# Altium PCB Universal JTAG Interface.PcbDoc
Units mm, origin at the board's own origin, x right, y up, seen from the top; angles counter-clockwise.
Board outline 60 x 39.3 mm, 2 copper layers (Top Layer, Bottom Layer); 81 components, 60 nets, 244 pads, 77 vias.
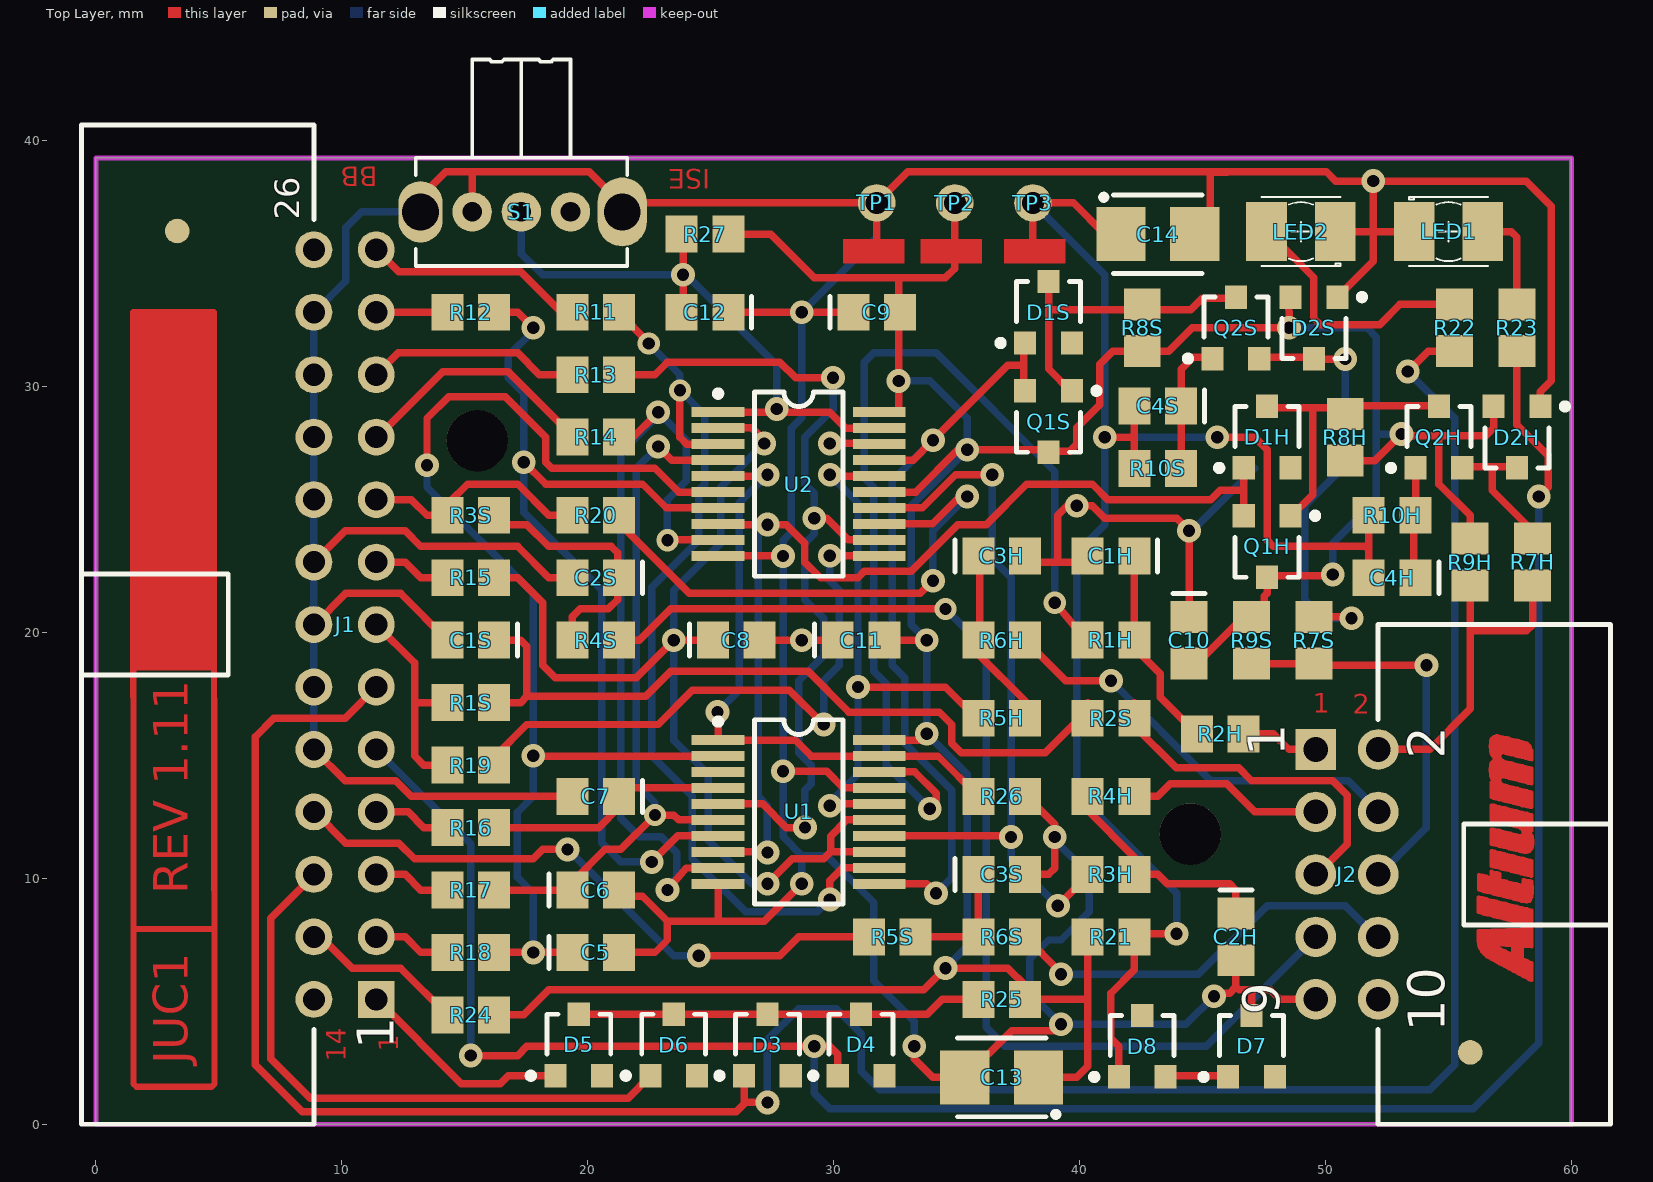
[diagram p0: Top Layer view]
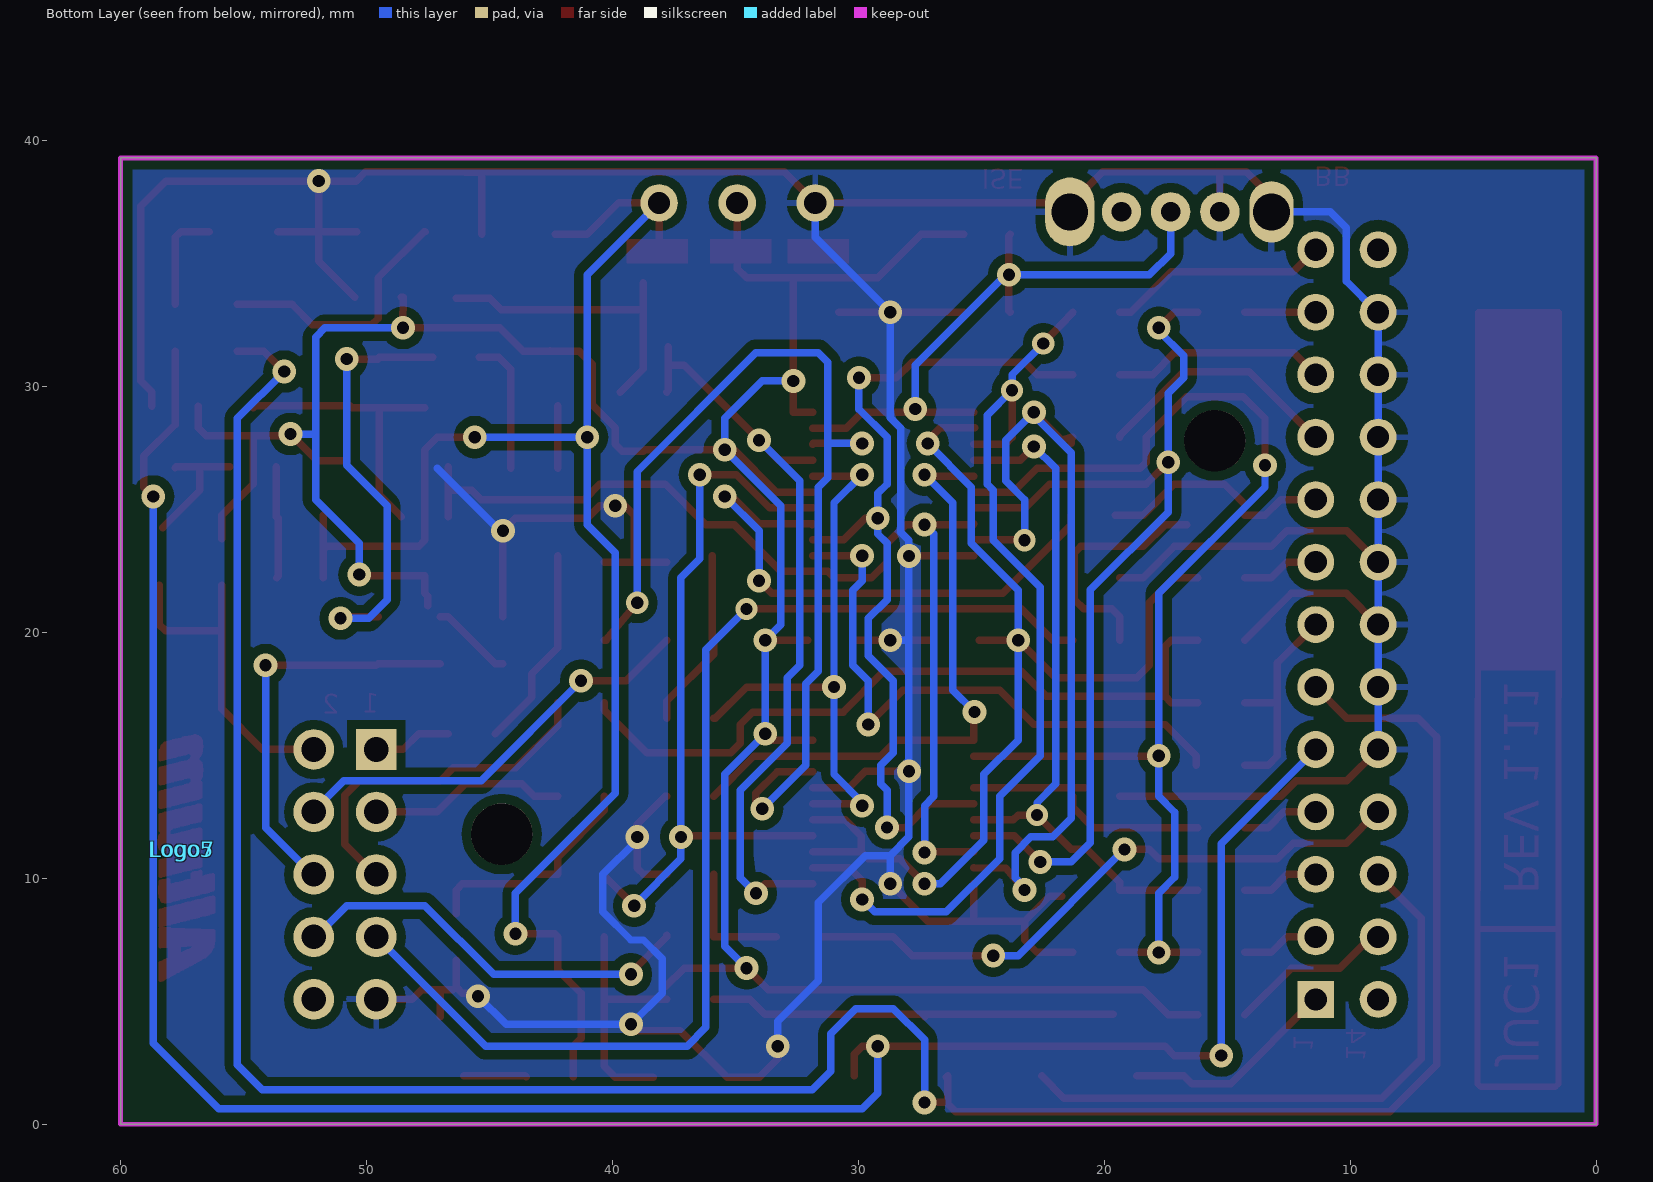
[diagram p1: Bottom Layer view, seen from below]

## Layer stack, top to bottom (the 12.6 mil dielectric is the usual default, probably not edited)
Top Layer: signal copper 0.0356
Dielectric: dielectric 0.32, FR-4, Dk 4.8
Bottom Layer: signal copper 0.0356

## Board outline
0,0 60,0 60,39.3 0,39.3

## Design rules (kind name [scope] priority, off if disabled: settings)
Clearance "Polygon Clearance" [InPolygon] p1: gap=0.381
Clearance "Via-Via Clearance" [IsVia vs IsVia] p2: gap=0.3
Clearance "Via-SMD Pad Clearance" [IsVia vs IsPad And OnTopLayer] p3: gap=0.254
Clearance "Via-Pad Clearance" [IsVia vs IsPad] p4: gap=0.3
Clearance "IC Pad-Pad Clearance" [HasFootprint('SOP65P780-20') vs HasFootprint('SOP65P780-20')] p5: gap=0.203
Clearance "General Clearance" [All] p6: gap=0.254
ComponentClearance ComponentClearance_General [Not InComponent('Logo5') && Not InComponent('Logo7') vs Not InComponent('Logo5') && Not InComponent('Logo7')] p1: gap=0.254 collisioncheckmode=3 verticalgap=0.254 showdistances=FALSE
ComponentClearance ComponentClearance_Default [All] p2 off: gap=0.254 collisioncheckmode=3 verticalgap=0.254 showdistances=FALSE
FabricationTestPointUsage TestPointUsage [All] p1 off: valid=0 allowmultiple=FALSE
FabricationTestpoint Testpoint [All] p1 off: side=3 testpointundercomponent=TRUE minsize=1.016 maxsize=2.54 preferedsize=1.524 minholesize=0 maxholesize=1.016 preferedholesize=0.813 testpointgrid=0.025 allowsidetop=TRUE allowsidebottom=TRUE usegrid=TRUE gridtolerance=0
HoleSize [All] p1: absolutevalues=TRUE maxlimit=3.2 minlimit=0.4 maxpercent=80.000 minpercent=20.000
PolygonConnect [All] p1: connectstyle=Relief reliefconductorwidth=0.254 reliefentries=4 polygonreliefangle="90 Angle"
RoutingVias [All] p1: holewidth=0.483 width=0.965 viastyle="Through Hole" minholewidth=0.3 minwidth=0.6 maxholewidth=0.711 maxwidth=1.27
SMDNeckDown [All] p1: percent=90.000
SilkscreenOverComponentPads [All] p1: minsilkscreentomaskgap=0.254
SolderMaskExpansion [All] p1: expansion=0.102
Width "Logo Component Track Width" [InComponent('Logo5') Or InComponent('Logo7')] p1: maxlimit=2.54 minlimit=0.127 preferedwidth=0.254
Width "Polygon Width" [InPolygon] p2: maxlimit=0.508 minlimit=0.203 preferedwidth=0.254
Width [All] p3: maxlimit=1.27 minlimit=0.254 preferedwidth=0.305
23 further rules are at their usual default settings.

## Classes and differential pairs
component class H: C1H C2H C3H C4H D1H D2H Q1H Q2H R1H R2H R3H R4H R5H R6H R7H R8H R9H R10H
component class "Universal JTAG Interface": C5 C6 C7 C8 C9 C10 C11 C12 C13 C14 D3 D4 D5 D6 D7 D8 J1 J2 LED1 LED2 R11 R12 R13 R14 R15 R16 R17 R18 R19 R20 R21 R22 R23 R24 R25 R26 R27 S1 TP1 TP2 TP3 U1 U2
component class S: C1S C2S C3S C4S D1S D2S Q1S Q2S R1S R2S R3S R4S R5S R6S R7S R8S R9S R10S
channel class "JTAG Interface": H S

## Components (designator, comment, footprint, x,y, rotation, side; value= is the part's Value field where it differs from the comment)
C1H "47pF 50V" CAPC2012 41.275,23.114 r180 top (schematic designator C1)
C1S "47pF 50V" CAPC2012 15.24,19.685 r180 top (schematic designator C1)
C2H "47pF 50V" CAPC2012 46.355,7.62 r270 top (schematic designator C2)
C2S "47pF 50V" CAPC2012 20.32,22.225 r180 top (schematic designator C2)
C3H "47pF 50V" CAPC2012 36.83,23.114 r0 top (schematic designator C3)
C3S "47pF 50V" CAPC2012 36.83,10.16 r0 top (schematic designator C3)
C4H "47pF 50V" CAPC2012 52.705,22.225 r180 top (schematic designator C4)
C4S "47pF 50V" CAPC2012 43.18,29.21 r180 top (schematic designator C4)
C5 "47pF 50V" CAPC2012 20.32,6.985 r0 top
C6 "47pF 50V" CAPC2012 20.32,9.525 r0 top
C7 "47pF 50V" CAPC2012 20.32,13.335 r180 top
C8 "47pF 50V" CAPC2012 26.035,19.685 r0 top
C9 "10nF 50V" CAPC2012 31.75,33.02 r0 top
C10 "10nF 50V" CAPC2012 44.45,19.685 r270 top
C11 "10nF 50V" CAPC2012 31.115,19.685 r0 top
C12 "10nF 50V" CAPC2012 24.765,33.02 r180 top
C13 "10uF 16V" CAPC3528 36.83,1.905 r180 top
C14 "10uF 16V" CAPC3528 43.18,36.195 r0 top
D1H "200mA 30V" SOT95P230-3 47.625,27.94 r0 top (schematic designator D1)
D1S "200mA 30V" SOT95P230-3 38.735,33.02 r0 top (schematic designator D1)
D2H "215mA 85V" SOT95P230-3 57.785,27.94 r180 top (schematic designator D2)
D2S "215mA 85V" SOT95P230-3 49.53,32.385 r180 top (schematic designator D2)
D3 "200mA 30V" SOT95P230-3 27.305,3.225 r0 top
D4 "200mA 30V" SOT95P230-3 31.115,3.225 r0 top
D5 "200mA 30V" SOT95P230-3 19.635,3.225 r0 top
D6 "200mA 30V" SOT95P230-3 23.495,3.225 r0 top
D7 "200mA 30V" SOT95P230-3 46.99,3.175 r0 top
D8 "215mA 85V" SOT95P230-3 42.545,3.175 r0 top
J1 "2x13 RA HEADER" HDR2X13_RA_CENTRONICS 8.86,20.32 r90 top locked
J2 "2x5 RA HEADER" 918510x323 52.14,10.16 r270 top locked
LED1 "ORANGE" LED3528 55,36.3 r180 top locked
LED2 "ORANGE" LED3528 49,36.3 r0 top
Logo5 "" "Altium Logo Small Bottom"#1 57.534,11.167 r270 bottom
Logo7 "" "Altium Logo Small Bottom"#2 57.495,11.167 r270 bottom
Q1H "TRAN-NPN-75V-40V-6V-SOT23" SOT95P230-3 47.625,23.495 r180 top (schematic designator Q1)
Q1S "TRAN-NPN-75V-40V-6V-SOT23" SOT95P230-3 38.735,28.575 r180 top (schematic designator Q1)
Q2H "TRAN-NPN-75V-40V-6V-SOT23" SOT95P230-3 54.61,27.94 r0 top (schematic designator Q2)
Q2S "TRAN-NPN-75V-40V-6V-SOT23" SOT95P230-3 46.355,32.385 r0 top (schematic designator Q2)
R1H "47R 5%" RESC2012 41.275,19.685 r0 top (schematic designator R1)
R1S "47R 5%" RESC2012 15.24,17.145 r0 top (schematic designator R1)
R2H "47R 5%" RESC2012 45.72,15.875 r0 top (schematic designator R2)
R2S "47R 5%" RESC2012 41.275,16.51 r0 top (schematic designator R2)
R3H "47R 5%" RESC2012 41.275,10.16 r0 top (schematic designator R3)
R3S "47R 5%" RESC2012 15.24,24.765 r0 top (schematic designator R3)
R4H "47R 5%" RESC2012 41.275,13.335 r0 top (schematic designator R4)
R4S "47R 5%" RESC2012 20.32,19.685 r0 top (schematic designator R4)
R5H "47R 5%" RESC2012 36.83,16.51 r0 top (schematic designator R5)
R5S "47R 5%" RESC2012 32.385,7.62 r0 top (schematic designator R5)
R6H "47R 5%" RESC2012 36.83,19.685 r0 top (schematic designator R6)
R6S "47R 5%" RESC2012 36.83,7.62 r0 top (schematic designator R6)
R7H "47R 5%" RESC2012 58.42,22.86 r90 top (schematic designator R7)
R7S "47R 5%" RESC2012 49.53,19.685 r90 top (schematic designator R7)
R8H "2K2 5%" RESC2012 50.8,27.94 r270 top (schematic designator R8)
R8S "2K2 5%" RESC2012 42.545,32.385 r270 top (schematic designator R8)
R9H "6K8 5%" RESC2012 55.88,22.86 r90 top (schematic designator R9)
R9S "6K8 5%" RESC2012 46.99,19.685 r90 top (schematic designator R9)
R10H "470R 5%" RESC2012 52.705,24.765 r0 top (schematic designator R10)
R10S "470R 5%" RESC2012 43.18,26.67 r0 top (schematic designator R10)
R11 "47R 5%" RESC2012 20.32,33.02 r180 top
R12 "47R 5%" RESC2012 15.24,33.02 r180 top
R13 "47R 5%" RESC2012 20.32,30.48 r180 top
R14 "47R 5%" RESC2012 20.32,27.94 r180 top
R15 "47R 5%" RESC2012 15.24,22.225 r180 top
R16 "47R 5%" RESC2012 15.24,12.065 r180 top
R17 "47R 5%" RESC2012 15.24,9.525 r180 top
R18 "47R 5%" RESC2012 15.24,6.985 r180 top
R19 "47R 5%" RESC2012 15.24,14.605 r0 top
R20 "47R 5%" RESC2012 20.32,24.765 r0 top
R21 "2K2 5%" RESC2012 41.275,7.62 r180 top
R22 "220R 5%" RESC2012 55.245,32.385 r270 top
R23 "220R 5%" RESC2012 57.785,32.385 r270 top
R24 "6K8 5%" RESC2012 15.24,4.445 r180 top
R25 "22R 5%" RESC2012 36.83,5.08 r180 top
R26 "47K 5%" RESC2012 36.83,13.335 r0 top
R27 "47K 5%" RESC2012 24.765,36.195 r180 top
S1 "SPDT SUB" OS102011MA1QN1 17.3,37.1 r180 top locked
TP1 "(GND)" TestPin 31.75,37.465 r0 top
TP2 "(VCC)" TestPin 34.925,37.465 r90 top
TP3 "(Vref)" TestPin 38.1,37.465 r90 top
U1 "SN74LVC244ADB" SOP65P780-20 28.575,12.7 r270 top
U2 "SN74LVC244ADB" SOP65P780-20 28.575,26.035 r270 top

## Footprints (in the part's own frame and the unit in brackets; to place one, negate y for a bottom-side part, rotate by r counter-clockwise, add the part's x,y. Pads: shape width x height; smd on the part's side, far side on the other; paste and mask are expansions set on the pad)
918510x323 [mm]
  rect 1.65x1.65 hole 1: 1(-5.08,-2.54)
  round 1.65 hole 1: 2(-5.08,0) 3(-2.54,-2.54) 4(-2.54,0) 5(0,-2.54) 6(0,0) 7(2.54,-2.54) 8(2.54,0) 9(5.08,-2.54) 10(5.08,0)
  silkscreen extent -10.16,0 10.16,9.45
"Altium Logo Small Bottom"#1 [mm]
  Bottom Layer drawing of 687 lines, arcs and shapes, not listed
"Altium Logo Small Bottom"#2 [mm]
CAPC2012 [mm]
  rect 1.3x1.5 smd: 1(-0.95,0) 2(0.95,0)
  silkscreen extent -1.9,-0.65 -1.9,0.65
CAPC3528 [mm]
  rect 2x2.2 smd: 1(-1.5,0) 2(1.5,0)
  silkscreen extent -2.3,-1.6 1.8,1.6
HDR2X13_RA_CENTRONICS [mm]
  rect 1.5x1.5 hole 0.9: 1(-15.24,-2.54)
  round 1.5 hole 0.9: 2(-12.7,-2.54) 3(-10.16,-2.54) 4(-7.62,-2.54) 5(-5.08,-2.54) 6(-2.54,-2.54) 7(0,-2.54) 8(2.54,-2.54) 9(5.08,-2.54) 10(7.62,-2.54) 11(10.16,-2.54) 12(12.7,-2.54) 13(15.24,-2.54) 14(-15.24,0) 15(-12.7,0) 16(-10.16,0) 17(-7.62,0) 18(-5.08,0) 19(-2.54,0) 20(0,0) 21(2.54,0) 22(5.08,0) 23(7.62,0) 24(10.16,0) 25(12.7,0) 26(15.24,0)
  silkscreen extent -20.32,0 20.32,9.45
LED3528 [mm]
  rect 1.65x2.41 smd: 1(-1.4,0) 2(1.4,0)
  silkscreen extent -1.6,-1.4 1.6,1.4
OS102011MA1QN1 [mm]
  round 1.6 hole 0.8: 1(-2,0) 2(0,0) 3(2,0)
  oval 2x2.8 / inner round 2 / far side oval 2x2.8 hole 1.5: M1(-4.1,0)
  oval 1.8x2.5 / inner oval 1.8x2 / far side oval 1.8x2.5 hole 1.5: M2(4.1,0)
  silkscreen extent -4.3,-6.2 4.3,2.2
RESC2012 [mm]
  rect 1.3x1.5 smd: 1(-0.95,0) 2(0.95,0)
SOP65P780-20 [mm]
  rect 0.4x2.15 smd: 1(-2.925,-3.275) 2(-2.275,-3.275) 3(-1.625,-3.275) 4(-0.975,-3.275) 5(-0.325,-3.275) 6(0.325,-3.275) 7(0.975,-3.275) 8(1.625,-3.275) 9(2.275,-3.275) 10(2.925,-3.275) 11(2.925,3.275) 12(2.275,3.275) 13(1.625,3.275) 14(0.975,3.275) 15(0.325,3.275) 16(-0.325,3.275) 17(-0.975,3.275) 18(-1.625,3.275) 19(-2.275,3.275) 20(-2.925,3.275)
  silkscreen extent -3.8,-3.4 3.75,1.8
SOT95P230-3 [mm]
  rect 0.9x0.95 smd: 1(-0.95,-1.25) 2(0.95,-1.25) 3(0,1.25)
  silkscreen extent -2.07,-1.37 1.3,1.25
TestPin [mil]
  round 60 hole 35.43: 1(0,0)

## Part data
C1H C1S C2H C2S C3H C3S C4H C4S C5 C6 C7 C8 C9 C10 C11 C12: library part CAP-NP, "Capacitor"
C13 C14: library part CAP-P, "Polar Capacitor"
D1H D1S D3 D4 D5 D6 D7: library part DIO-SCHOTTKY-1S-SOT23, "Schottky Barrier Single Diode"
D2H D2S D8: library part DIO-2S, "Silicon Switching Diode Array for High-Speed Switching"
J1: library part CON-IDC-2x13-M-RA, "Header, 13-Pin, Dual row"
J2: library part CON-IDC-2x5-M-RA, "Header, 5-Pin, Dual row, Right angle boxed"
LED1 LED2: library part DIO-LED-1S, "Typical GREEN SMD LED Agilent make"
Q1H Q1S Q2H Q2S: library part TRA-NPN, "General Purpose Transistor NPN Silicon"
R1H R1S R2H R2S R3H R3S R4H R4S R5H R5S R6H R6S R7H R7S R8H R8S R9H R9S R10H R10S R11 R12 R13 R14 R15 R16 R17 R18 R19 R20 R21 R22 R23 R24 R25 R26 R27: library part RES, "Resistor"
S1: library part SWI-TOG-SPDT-OS102011MA1QN1, "SPDT Subminiature Toggle Switch"
TP1 TP2 TP3: library part TestPin
U1 U2: library part SN74LVC244, "Octal Buffer/Driver with 3-State Outputs"

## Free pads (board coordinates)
  round 2.49 hole 2.5 unplated: 0(15.5,27.8) 1(44.5,11.8)
  round 1 smd mask+1.6: FID(3.302,36.322) FID(55.88,2.921)

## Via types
v1: diameter 0.965, hole 0.5, Top Layer to Bottom Layer, tented both sides, 71 vias
v2: diameter 0.9, hole 0.5, Top Layer to Bottom Layer, tented both sides, 6 vias

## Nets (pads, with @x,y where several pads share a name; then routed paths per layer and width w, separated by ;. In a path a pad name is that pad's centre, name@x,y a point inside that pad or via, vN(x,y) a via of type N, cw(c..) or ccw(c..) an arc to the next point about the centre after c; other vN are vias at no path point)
BB/I\S\E\: R26.1 U1.1 U1.19 U2.5 | length 25.2
  Top Layer w0.305: v1(25.273,16.764) 25.3,16.483 U1.1 28.444,15.625 29.094,14.975 U1.19 34.24,14.975 R26.1 ; U2.5 27.249,26.36 v1(27.305,26.416)
  Bottom Layer w0.305: v1(25.273,16.764) 26.162,17.653 26.162,25.273 v1(27.305,26.416)
"COMPATIBILITY MODE": C12.2 R27.2 S1.2 U2.1 U2.19 | length 25.8
  Top Layer w0.305: C12.2 23.876,33.081 v1(23.876,34.544) 23.876,36.134 R27.2 ; U2.1 27.686,28.96 29.841,28.96 30.491,28.31 U2.19
  Bottom Layer w0.305: S1.2 17.3,35.405 18.161,34.544 v1(23.876,34.544) 24.003,34.544 27.686,30.861 v1(27.686,29.087)
GND: C1H.2 C1S.2 C2H.2 C2S.2 C3H.2 C3S.2 C5.2 C6.2 C7.2 C8.2 C9.1 C10.1 C11.1 C12.1 C13.2 C14.2 D2H.1 D2S.1 D7.3 J1.18 J1.19 J1.20 J1.21 J1.22 J1.23 J1.24 J1.25 J2.9 LED1.2 LED2.2 R26.2 S1.3 S1.M1 S1.M2 TP1.1 U1.10 U1.17 U2.10 | length 248
  Top Layer w0.305: J1.18 10.13,13.97 12.192,13.97 12.827,13.335 C7.2 ; J1.20 8.89,20.32 10.16,21.59 12.385,21.59 C1S.2 ; J1.21 10.13,24.13 12.573,24.13 13.208,23.495 17.145,23.495 18.415,22.225 C2S.2 ; S1.M2@13.208,37.719 14.224,38.735 15.367,38.735 ; S1.3 15.3,38.668 15.367,38.735 ; C5.2 22.733,6.985 23.241,7.493 23.241,8.255 ; S1.M1 21.4,37.401 20.066,38.735 15.367,38.735 ; C6.2@21.717,9.271 22.225,9.271 23.241,8.255 ; S1.M1@21.971,37.592 22.098,37.465 TP1.1 ; U1.10@25.296,9.779 U1.10 25.3,8.282 ; U2.10 v1(27.94,23.11) ; C12.1 v1(28.702,33.02) C9.1 ; C8.2 v1(28.702,19.685) C11.1 ; v1(27.94,14.351) 29.718,14.351 30.394,13.675 U1.17 ; v1@28.698,9.775 27.178,8.255 23.241,8.255 ; 31.75,35.687 TP1.1 ; v1(33.274,3.175) 33.274,2.667 34.036,1.905 C13.2 37.235,3.81 38.989,3.81 v1(39.243,4.064) ; C3S.2 38.735,10.16 38.989,10.414 v1(38.989,11.684) 38.989,12.192 37.846,13.335 R26.2 ; C3H.2@37.78,22.86 39.116,22.86 ; C1H.2@40.325,22.86 39.116,22.86 ; C10.1 v1(44.45,24.13) 43.942,24.638 41.021,24.638 40.513,25.146 v1(39.878,25.146) 39.497,25.146 39.116,24.765 39.116,22.86 ; C14.2@45.315,36.195 45.315,38.711 ; v1(45.466,5.207) 45.593,5.334 46.101,5.334 46.355,5.588 ; 45.998,38.711 45.315,38.711 ; C2H.2 46.355,5.588 ; D7.3@46.99,4.375 46.99,5.461 ; J2.9 48.133,5.08 47.752,5.461 46.99,5.461 ; LED2.2 51.921,36.3 ; D2S.1 51.943,35.098 51.943,36.3 ; LED1.2 51.943,36.3 ; D2H.1 58.735,29.779 59.182,30.226 59.182,37.338 58.166,38.354 v1(51.943,38.354) ; TP1.1 33.02,38.735 45.339,38.735 ; 45.315,38.711 45.339,38.735 ; 45.339,38.735 50.038,38.735 50.419,38.354 v1(51.943,38.354) ; 46.355,5.588 46.482,5.461 46.99,5.461 ; 51.921,36.3 51.943,36.322 ; 51.921,36.3 51.943,36.3 ; 51.943,36.3 51.943,36.322 ; 51.943,36.322 v1(51.943,38.354)
  Bottom Layer w0.305: J1.18 J1.19 J1.20 J1.21 J1.22 J1.23 J1.24 J1.25 8.89,33.02 10.16,34.29 10.16,36.449 10.811,37.1 S1.M2 ; v1(28.702,9.779) 28.702,10.922 ; v1(28.702,19.685) 28.067,19.685 27.94,19.812 ; TP1.1 31.75,36.068 v1(28.702,33.02) 28.702,28.73 28.27,28.298 28.27,24.079 27.94,23.749 v1(27.94,23.11) 27.94,19.812 ; v1(33.274,3.175) 33.274,4.191 31.623,5.842 31.623,9.017 29.718,10.922 28.702,10.922 ; v1(38.989,11.684) 38.989,11.557 40.386,10.16 40.386,8.636 39.243,7.493 38.735,7.493 37.973,6.731 37.973,5.334 v1(39.243,4.064) 44.323,4.064 v1(45.466,5.207) ; v1(44.45,24.13) 44.577,24.13 47.117,26.67 ; v1@51.89,38.376 v1@51.9,38.4 ; 27.94,19.812 v1(27.94,14.351) 27.94,11.684 28.702,10.922
HARD-TCK: J2.3 R4H.2 | length 8.1
  Top Layer w0.305: R4H.2 43.18,13.335 43.688,13.843 45.974,13.843 47.117,12.7 J2.3
HARD-TDI: J2.1 R2H.2 | length 3.2
  Top Layer w0.305: R2H.2 47.879,15.875 48.514,15.24 J2.1
HARD-TDO: J2.2 R7H.1 R9H.1 | length 13.7
  Top Layer w0.305: J2.2 54.229,15.24 55.88,16.891 55.88,20.066 ; R9H.1 55.88,20.066 ; R7H.1 58.42,20.32 58.166,20.066 55.88,20.066
HARD-TMS: J2.4 R6H.2 | length 17.3
  Top Layer w0.305: R6H.2 39.431,18.034 v1(41.275,18.034)
  Bottom Layer w0.305: v1(41.275,18.034) 45.339,13.97 50.927,13.97 52.14,12.757 J2.4
HARD_TCK_IN: R3H.1 U1.14 U2.14 | length 30.9
  Top Layer w0.305: U1.14 v1@37.17,11.725 ; U2.14 33.597,25.06 34.953,26.416 v1(36.449,26.416) ; v1(39.116,8.89) 40.325,10.099 R3H.1
  Bottom Layer w0.305: v1(36.449,26.416) 36.449,22.987 37.211,22.225 v1(37.211,11.684) 37.211,10.795 v1(39.116,8.89)
HARD_TDI_IN: R1H.1 U1.18 U2.18 | length 43.4
  Top Layer w0.305: v1(29.845,27.686) 31.824,27.686 U2.18 ; U1.18 33.3,14.325 34.163,13.462 34.163,13.081 v1(33.909,12.827) ; v2(38.989,21.209) 40.259,19.685 R1H.1
  Bottom Layer w0.305: v1(29.845,27.686) 31.242,27.686 ; v1(33.909,12.827) 32.131,14.605 32.131,17.907 31.623,18.415 31.623,25.908 31.242,26.289 31.242,27.686 ; v2(38.989,21.209) 38.989,26.543 34.163,31.369 31.623,31.369 31.242,30.988 31.242,27.686
HARD_TDO_OUT: D1H.1 Q1H.2 U1.8 U2.8 | length 42.4
  Top Layer w0.305: U1.8 v1@27.279,11.075 ; U2.8 25.326,24.384 v1(27.305,24.384) 28.067,24.384 28.829,23.622 28.829,22.86 29.464,22.225 30.988,22.225 31.242,22.479 33.147,22.479 35.052,24.384 36.195,24.384 37.846,26.035 40.513,26.035 41.148,25.4 45.339,25.4 45.72,25.781 46.675,25.781 ; Q1H.2@46.675,24.695 46.675,25.781 ; D1H.1@46.675,26.74 46.675,25.781
  Bottom Layer w0.305: v1(27.305,11.049) 27.305,12.954 26.924,13.335 26.924,24.003 v1(27.305,24.384)
HARD_TMS_IN: R5H.1 U1.16 U2.16 | length 23.9
  Top Layer w0.305: v1(29.845,12.954) 29.916,13.025 U1.16 ; v1(29.845,26.416) 29.901,26.36 U2.16 ; v1(30.988,17.78) 34.544,17.78 35.814,16.51 R5H.1
  Bottom Layer w0.305: v1(29.845,12.954) 29.845,13.081 30.988,14.224 v1(30.988,17.78) 30.988,25.273 v1(29.845,26.416)
NetC1H_1: C1H.1 R1H.2 R2H.1 | length 8.3
  Top Layer w0.305: C1H.1 R1H.2 42.225,19.37 43.282,18.313 43.282,17.363 R2H.1
NetC1S_1: C1S.1 R1S.2 R2S.1 | length 31
  Top Layer w0.305: R1S.2 17.272,17.145 17.526,17.399 ; C1S.1 17.272,19.685 17.526,19.431 17.526,17.399 ; R2S.1@40.325,17.145 40.325,16.83 40.165,16.67 38.608,15.113 35.179,15.113 34.798,15.494 34.798,16.256 34.29,16.764 30.607,16.764 28.956,18.415 23.368,18.415 22.352,17.399 17.526,17.399
NetC2H_1: C2H.1 R3H.2 R4H.1 | length 9.3
  Top Layer w0.305: R4H.1 40.325,12.761 42.225,10.861 R3H.2 43.18,10.16 43.561,9.779 46.101,9.779 46.355,9.525 C2H.1
NetC2S_1: C2S.1 R3S.2 R4S.1 | length 10
  Top Layer w0.305: R3S.2@16.637,24.384 17.526,24.384 18.415,23.495 20.955,23.495 21.209,23.241 21.209,22.225 21.209,21.336 20.828,20.955 19.685,20.955 19.37,20.64 R4S.1
NetC3H_1: C3H.1 R5H.2 R6H.1 | length 7.4
  Top Layer w0.305: C3H.1@35.941,23.114 35.941,19.746 R6H.1 35.88,19.111 37.78,17.211 R5H.2
NetC3S_1: C3S.1 R5S.2 R6S.1 | length 5.1
  Top Layer w0.305: R5S.2 R6S.1 C3S.1
NetC4H_1: C4H.1 Q2H.1 R10H.2 | length 4.6
  Top Layer w0.305: C4H.1 53.594,22.286 53.594,24.638 53.66,24.704 53.66,24.765 Q2H.1@53.66,26.74
NetC4S_1: C4S.1 Q2S.1 R10S.2 | length 5.5
  Top Layer w0.305: R10S.2 C4S.1 44.13,30.693 44.622,31.185 Q2S.1@45.405,31.185
NetD1H_3: D1H.3 Q1H.1 Q2H.3 R8H.1 | length 11.9
  Top Layer w0.305: D1H.3@47.625,29.14 49.479,29.14 ; Q1H.1@48.575,24.695 49.479,25.599 49.479,29.14 ; Q2H.3@54.61,29.14 54.54,29.21 50.8,29.21 50.673,29.21 50.603,29.14 49.479,29.14
NetD1S_3: D1S.3 Q1S.1 Q2S.3 R8S.1 | length 12.7
  Top Layer w0.305: D1S.3@38.735,34.22 38.735,33.122 ; Q1S.1@39.685,29.775 38.735,30.725 38.735,33.122 ; Q2S.3@46.355,33.585 44.99,33.585 44.526,33.122 42.545,33.122 38.735,33.122
NetD2H_3: D2H.3 Q2H.2 R7H.2 | length 5.4
  Top Layer w0.305: Q2H.2@55.56,26.74 56.769,26.74 ; D2H.3 57.735,26.74 56.769,26.74 ; R7H.2@58.293,24.257 56.769,25.781 56.769,26.74
NetD2S_3: D2S.3 Q2S.2 R7S.2 | length 17.8
  Top Layer w0.305: Q2S.2@47.305,31.185 49.48,31.185 D2S.3 49.55,31.115 v1(50.8,31.115) ; R7S.2 50.993,20.635 v1(51.054,20.574)
  Bottom Layer w0.305: v1(50.8,31.115) 50.8,26.797 49.149,25.146 49.149,21.336 49.911,20.574 v1(51.054,20.574)
NetD3_3: D3.3 D4.3 D5.3 D6.3 R25.2 | length 16.5
  Top Layer w0.305: D5.3 D3.3 D4.3 33.812,4.475 34.417,5.08 R25.2
NetD7_1: D7.1 D8.2 | length 2.6
  Top Layer w0.305: D8.2 43.545,1.975 D7.1@46.04,1.975
NetJ1_2: J1.2 R18.2 | length 3.2
  Top Layer w0.305: J1.2 12.573,7.62 13.208,6.985 R18.2
NetJ1_3: J1.3 R17.2 | length 3.2
  Top Layer w0.305: J1.3 12.573,10.16 13.208,9.525 R17.2
NetJ1_4: J1.4 R16.2 | length 3.2
  Top Layer w0.305: J1.4 12.7,12.7 13.335,12.065 R16.2
NetJ1_8: J1.8 R15.2 | length 3.2
  Top Layer w0.305: J1.8 12.573,22.86 13.208,22.225 R15.2
NetJ1_10: J1.10 R14.2 | length 10.2
  Top Layer w0.305: J1.10 11.43,27.94 14.097,30.607 16.764,30.607 19.37,28.001 R14.2
NetJ1_11: J1.11 R13.2 | length 8.7
  Top Layer w0.305: J1.11 12.289,31.369 17.145,31.369 18.034,30.48 R13.2
NetJ1_12: J1.12 R12.2 | length 2.9
  Top Layer w0.305: J1.12 R12.2
NetJ1_13: J1.13 R11.2 | length 9
  Top Layer w0.305: J1.13 11.43,35.56 12.319,34.671 17.272,34.671 18.923,33.02 R11.2
NetJ1_15: J1.15 R24.2 | length 6.7
  Top Layer w0.305: J1.15 9.144,7.62 10.414,6.35 12.385,6.35 R24.2
NetLED1_1: LED1.1 R23.1 | length 4.2
  Top Layer w0.305: LED1.1 57.553,36.3 57.785,36.068 R23.1
NetLED2_1: LED2.1 R22.1 | length 10.5
  Top Layer w0.305: LED2.1 47.647,36.3 49.53,34.417 49.53,32.766 49.784,32.512 52.197,32.512 53.02,33.335 R22.1
NetR19_2: R19.2 U2.11 | length 24.7
  Top Layer w0.305: R19.2@16.256,14.605 16.256,14.986 17.526,16.256 22.86,16.256 24.257,17.653 28.194,17.653 v1(29.591,16.256) ; v1(29.845,23.114) 30.095,23.11 U2.11
  Bottom Layer w0.305: v1(29.591,16.256) 29.591,18.034 30.226,18.669 30.226,21.717 29.845,22.098 v1(29.845,23.114)
NetR20_2: R20.2 U2.13 | length 22.5
  Top Layer w0.305: R20.2@21.336,24.765 21.336,24.384 24.13,21.59 33.528,21.59 v1(34.036,22.098) ; U2.13@31.876,24.384 U2.13 34.01,24.41 35.127,25.527 v1(35.433,25.527)
  Bottom Layer w0.305: v1(34.036,22.098) 34.036,24.13 v1(35.433,25.527)
PP_02_D0_OUT: C5.1 R18.1 U1.2 U2.6 | length 49.1
  Top Layer w0.305: v1(13.462,26.797) 13.462,28.702 14.351,29.591 16.637,29.591 18.288,27.94 18.288,26.924 18.542,26.67 22.733,26.67 23.693,25.71 U2.6 ; R18.1 v1(17.78,6.985) C5.1 ; v1(17.78,14.986) 17.791,14.975 U1.2
  Bottom Layer w0.305: v1(13.462,26.797) 13.462,25.908 17.78,21.59 v1(17.78,14.986) 17.78,13.335 17.142,12.697 17.142,10.036 17.78,9.398 v1(17.78,6.985)
PP_03_D1_OUT: C6.1 R17.1 U1.6 U2.4 | length 29
  Top Layer w0.305: R17.1 C6.1 19.37,9.845 20.701,11.176 21.336,11.176 v2(22.733,12.573) 23.495,12.573 23.693,12.375 U1.6 ; v1(22.86,27.559) 23.409,27.01 U2.4
  Bottom Layer w0.305: v2(22.733,12.573) 22.733,13.081 21.971,13.843 21.971,26.67 v1(22.86,27.559)
PP_04_D2_OUT: C7.1 R16.1 U1.4 | length 10.4
  Top Layer w0.305: R16.1 20.447,12.065 21.27,12.888 C7.1 ; C7.1@20.787,13.675 21.27,13.675 U1.4
PP_05_D3_OUT: D4.1 J1.5 R23.2 | length 91.7
  Top Layer w0.305: v1(15.24,2.794) 17.145,2.794 17.526,3.175 29.845,3.175 30.165,2.855 D4.1 ; R23.2 57.785,28.448 59.055,27.178 59.055,25.908 v1(58.674,25.527)
  Bottom Layer w0.305: J1.5 15.24,11.4 v1(15.24,2.794) ; v1(29.21,3.175) 29.21,1.27 29.845,0.635 56.007,0.635 58.674,3.302 v1(58.674,25.527)
PP_06_D4_OUT: D3.1 J1.6 R22.2 | length 107
  Top Layer w0.305: J1.6 10.13,16.51 7.239,16.51 6.477,15.748 6.477,2.413 8.382,0.508 26.035,0.508 26.416,0.889 v1(27.305,0.889) ; 26.355,0.828 D3.1 D3.1@26.416,1.914 ; v1(53.34,30.607) 54.168,31.435 R22.2
  Bottom Layer w0.305: v1(27.305,0.889) 27.305,3.429 28.575,4.699 30.099,4.699 31.115,3.683 31.115,2.159 31.877,1.397 54.229,1.397 55.245,2.413 55.245,28.702 v1(53.34,30.607)
PP_07_D5_OUT: J1.7 R1S.1 R19.1 | length 8.8
  Top Layer w0.305: J1.7 12.954,18.766 12.954,17.145 ; R19.1 13.335,14.605 12.954,14.986 12.954,17.145 ; R1S.1 12.954,17.145
PP_08_D6_OUT: C8.1 R15.1 U1.13 U1.15 U2.2 | length 44.3
  Top Layer w0.305: R15.1 17.145,22.225 18.161,21.209 18.161,18.669 18.669,18.161 21.971,18.161 v1(23.495,19.685) C8.1 ; U2.2@25.273,28.321 25.3,28.321 26.67,28.321 27.178,27.813 v1(27.178,27.686) ; v1(27.305,9.779) 28.321,10.795 29.591,10.795 29.871,11.075 ; U1.13 29.871,11.075 ; U1.15 30.536,12.375 29.871,11.71 29.871,11.075
  Bottom Layer w0.305: v1(27.178,27.686) 25.4,25.908 25.4,23.622 23.495,21.717 v1(23.495,19.685) 23.495,15.621 24.892,14.224 24.892,11.557 26.67,9.779 v1(27.305,9.779)
PP_09_D7_OUT: J1.9 R3S.1 R20.1 | length 9.2
  Top Layer w0.305: J1.9 12.827,25.4 13.462,24.765 R3S.1 ; R3S.1@14.351,25.273 15.113,26.035 17.145,26.035 18.415,24.765 R20.1 R20.1@19.558,24.765
PP_10_ACK_IN: R14.1 U1.9 U2.9 | length 34.4
  Top Layer w0.305: R14.1 R14.1@21.336,27.94 ; R14.1@21.336,27.686 R14.1@21.336,27.94 ; v1(22.86,28.956) 21.717,27.813 R14.1@21.336,27.94 ; v1(23.241,9.525) 24.003,10.414 U1.9 ; v2@23.379,23.76 U2.9
  Bottom Layer w0.305: v1(23.241,9.525) 23.241,9.652 23.622,10.033 23.622,11.049 22.987,11.684 22.098,11.684 21.336,12.446 21.336,27.305 22.86,28.829 v1(22.86,28.956) 24.003,27.813 24.003,26.162 23.241,25.4 v2(23.241,23.749)
PP_11_BSY_IN: R13.1 U1.5 U2.12 | length 36.2
  Top Layer w0.305: R13.1 22.733,30.48 23.241,30.988 27.813,30.988 28.448,30.353 v1(29.972,30.353) ; U1.5 27.107,13.025 28.067,12.065 v1(28.829,12.065) ; v1(29.21,24.638) 29.718,24.638 30.596,23.76 U2.12
  Bottom Layer w0.305: v1(28.829,12.065) 28.829,13.589 29.083,13.843 29.083,14.605 28.575,15.113 28.575,18.034 29.591,19.05 29.591,20.574 28.829,21.336 28.829,23.622 29.21,24.003 v1(29.21,24.638) 29.21,25.654 28.829,26.035 28.829,27.94 29.972,29.083 v1(29.972,30.353)
PP_12_PE_IN: R12.1 U1.7 U2.7 | length 39
  Top Layer w0.305: R12.1 17.145,33.02 v1(17.78,32.385) ; v1(17.399,26.924) 18.288,26.035 22.225,26.035 23.2,25.06 U2.7 ; v1(22.606,10.668) 23.663,11.725 U1.7
  Bottom Layer w0.305: v1(17.78,32.385) 17.78,32.258 16.764,31.242 16.764,30.353 17.399,29.718 v1(17.399,26.924) 17.399,24.892 20.56,21.731 20.56,11.444 21.336,10.668 v1(22.606,10.668)
PP_13_SEL_IN: R11.1 U1.12 U2.3 | length 38.5
  Top Layer w0.305: R11.1 v2@22.484,31.755 ; v2@24.003,29.718 23.939,29.654 23.749,29.464 23.749,27.94 24.029,27.66 U2.3 ; v1(29.845,9.144) 29.845,9.906 30.364,10.425 U1.12
  Bottom Layer w0.305: v2@22.484,31.755 22.484,31.75 22.484,31.745 23.749,30.48 v2(23.749,29.845) 24.765,28.829 24.765,26.035 24.511,25.781 24.511,23.749 22.606,21.844 22.606,14.986 24.257,13.335 24.257,10.795 26.416,8.636 29.337,8.636 v1(29.845,9.144)
  other v2: 22.479,31.75
PP_INIT: D6.1 J1.16 | length 24.7
  Top Layer w0.305: J1.16 8.86,10.13 7.112,8.382 7.112,2.667 8.712,1.067 21.637,1.067 D6.1
PP_SOFT_TMS: J1.17 R5S.1 | length 25.6
  Top Layer w0.305: J1.17 8.89,12.7 10.16,11.43 12.319,11.43 12.954,10.795 17.78,10.795 18.161,11.176 v1(19.177,11.176) ; v1(24.511,6.858) 27.813,6.858 28.575,7.62 R5S.1
  Bottom Layer w0.305: v1(19.177,11.176) 23.495,6.858 v1(24.511,6.858)
PP_STROBE: D5.1 J1.1 | length 8.8
  Top Layer w0.305: J1.1 11.43,5.08 14.859,1.651 16.44,1.651 16.764,1.975 D5.1
SOFT-TCK: J2.7 R4S.2 | length 47.1
  Top Layer w0.305: R4S.2 22.098,19.685 23.368,20.955 v2(34.544,20.955)
  Bottom Layer w0.305: v2(34.544,20.955) 36.195,19.304 36.195,3.937 36.957,3.175 45.155,3.175 J2.7
SOFT-TDI: J2.5 R2S.2 | length 14.5
  Top Layer w0.305: R2S.2@42.225,17.145 R2S.2 42.225,16.195 43.925,14.495 46.465,14.495 46.99,13.97 50.292,13.97 50.876,13.386 50.876,11.379 J2.5@49.657,10.16
SOFT-TDO: J2.6 R7S.1 R9S.1 | length 16.6
  Top Layer w0.305: R9S.1 R7S.1 49.596,18.669 v1(54.102,18.669) ; J2.6 J2.6@52.197,10.16
  Bottom Layer w0.305: J2.6 52.197,10.16 54.102,12.065 v1(54.102,18.669)
SOFT-TMS: J2.8 R6S.2 | length 16.8
  Top Layer w0.305: R6S.2@37.78,7.681 R6S.2 39.243,6.157 v1(39.243,6.096)
  Bottom Layer w0.305: v1(39.243,6.096) 44.831,6.096 47.625,8.89 50.8,8.89 52.07,7.62 J2.8
SOFT_TDO_OUT: D1S.1 Q1S.2 U1.11 U2.17 | length 32.2
  Top Layer w0.305: U1.11 33.786,9.775 v1(34.163,9.398) ; U2.17 33.233,27.01 v1(34.036,27.813) 37.084,30.861 37.719,30.861 ; D1S.1@37.719,31.623 37.719,30.861 ; Q1S.2@37.785,29.775 37.719,29.841 37.719,30.861
  Bottom Layer w0.305: v1(34.036,27.813) 32.385,26.162 32.385,18.669 32.893,18.161 32.893,15.494 34.798,13.589 34.798,10.033 v1(34.163,9.398)
VCC: C9.2 C10.2 C11.2 C13.1 D2H.2 D2S.2 Q1H.3 Q1S.3 R8H.2 R8S.2 R9H.2 R9S.2 R21.2 R24.1 R25.1 R27.1 TP2.1 U1.20 U2.15 U2.20 | length 140.2
  Top Layer w0.305: R24.1 17.399,4.445 18.415,5.461 33.655,5.461 v1(34.544,6.35) 37.084,6.35 R25.1@37.846,5.588 ; R27.1 27.432,36.195 29.21,34.417 32.639,34.417 ; U1.20 33.532,15.625 v1(33.782,15.875) ; U2.15 33.33,25.71 35.052,27.432 v1(35.433,27.432) 38.678,27.432 38.735,27.375 39.592,27.375 39.878,27.661 39.878,28.321 40.818,29.261 40.818,30.912 41.341,31.435 R8S.2 ; U2.20 U2.20@32.639,28.96 ; C11.2 v1(33.782,19.685) ; U2.20@32.639,28.956 U2.20@32.639,28.96 ; 34.925,35.56 34.925,34.798 34.544,34.417 32.639,34.417 ; 34.925,35.814 TP2.1 ; R25.1 40.325,5.08 ; C13.1 39.878,1.905 40.325,2.352 40.325,5.08 ; R21.2 40.325,5.08 ; R8S.2@42.555,31.445 R8S.2 ; C10.2 44.77,18.735 46.67,20.635 R9S.2 ; R9S.2@47.498,21.082 47.498,21.463 47.625,21.59 47.625,22.295 50.235,22.295 v1(50.292,22.352) ; D2S.2 48.494,33.635 48.494,33.634 48.514,32.512 v1(48.514,32.385) 44.577,32.385 43.627,31.435 R8S.2 ; R8H.2 52.009,26.99 53.02,28.001 53.086,28.001 54.61,28.001 ; R9H.2 55.88,24.765 54.61,26.035 54.61,28.001 ; D2H.2 56.835,28.321 56.515,28.001 54.61,28.001 ; U2.20@32.639,28.96 v1(32.639,30.226) 32.639,33.02 32.639,34.417
  Bottom Layer w0.305: v1(32.639,30.226) 33.909,30.226 35.433,28.702 v1(35.433,27.432) 33.147,25.146 33.147,20.32 v1(33.782,19.685) ; v1@33.782,19.812 v1(33.782,19.685) ; v1(34.544,6.35) 35.433,7.239 35.433,14.224 v1(33.782,15.875) v1(33.782,19.685) ; v1(48.514,32.385) 51.689,32.385 52.07,32.004 52.07,28.067 ; v1(50.292,22.352) 50.292,23.622 52.07,25.4 52.07,28.067 ; v1(53.086,28.067) 52.07,28.067
VREF: C4H.2 C4S.2 C14.1 D8.1 R10H.1 R10S.1 R21.1 TP3.1 | length 68.8
  Top Layer w0.305: 38.1,35.56 TP3.1 39.751,37.465 41.021,36.195 C14.1 C14.1@42.315,36.195 ; v1(41.021,27.94) 42.23,27.94 ; D8.1 41.595,3.175 41.275,3.495 41.275,5.334 42.225,6.284 R21.1 42.352,7.747 v1(43.942,7.747) ; R10S.1 42.23,27.94 ; C4S.2 42.23,27.94 ; v1(45.593,27.94) 47.117,27.94 47.625,27.432 47.625,23.749 47.879,23.495 51.628,23.495 51.755,23.368 ; C4H.2 51.755,23.368 ; R10H.1 51.755,23.368
  Bottom Layer w0.305: TP3.1 41.021,34.544 v1(41.021,27.94) ; v1(43.942,7.747) 43.942,9.398 39.878,13.462 39.878,23.241 41.021,24.384 v1(41.021,27.94) ; v1(45.593,27.94) v1(41.021,27.94)
pads on no net: D1H.2 D1S.2 D3.2 D4.2 D5.2 D6.2 D7.2 D8.3 J1.14 J1.26 J2.10 S1.1 U1.3
copper on no net: | length 72.7
  Top Layer w0.254: 1.524,7.945 4.826,7.945 ; 1.515,33.02 4.79,33.02 4.826,1.651 4.699,1.524 1.651,1.524 1.524,1.651 1.515,33.02

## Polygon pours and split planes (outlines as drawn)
GND on Bottom Layer "Bottom Layer-GND" (solid, remove dead copper, pour order 1000): -1.016,40.132 60.833,40.132 60.833,-0.889 -1.016,-0.889

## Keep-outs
Keep-Out Layer:
  the board outline again, w0.2

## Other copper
Top Layer:
  region: 1.515,33.02 1.515,18.445 4.79,18.445 4.79,33.02
  rectangle net GND: 30.378,35.007 32.878,36.007
  rectangle net VCC: 33.528,35.007 36.028,36.007
  rectangle net VREF: 36.932,35.007 39.432,36.007
  text "BB" at 11.452,38.928 h0.8 r180
  text "ISE" at 24.979,38.828 h0.8 r180
  text "1" at 49.489,16.728 h0.8
  text "2" at 51.1,16.7 h0.8
  text "REV 1.11" at 3.728,9.345 h1.4 r90
  text "1" at 12.286,2.946 h0.8 r90
  text "14" at 10.16,2.54 h0.8 r90
  text "JUC1" at 3.728,2.445 h1.4 r90
Bottom Layer:
  pour cut-out: 8.4,14.2 9.3,14.2 9.3,13.8 8.4,13.8
  pour cut-out: 8.4,34.5 9.3,34.5 9.3,34.1 8.4,34.1

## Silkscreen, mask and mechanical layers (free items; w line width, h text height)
Top Solder:
  region: 1.378,33.147 1.378,18.445 4.978,18.445 4.978,33.147
  lines w0.597: 1.678,1.461 1.524,1.615 1.524,33.02 4.7,33 4.7,32.83 4.765,32.765 4.765,1.501
  lines w0.6: 1.653,7.945 4.638,7.945 ; 4.638,29.466 1.653,29.466 1.653,16.684 1.653,1.486 1.678,1.461 4.678,1.461 4.765,1.501
  text "BB" at 11.452,38.928 h0.8 r180
  text "ISE" at 24.979,38.828 h0.8 r180
  text "TP1" at 30.69,35.088 h0.8
  text "TP2" at 33.753,35.088 h0.8
  text "TP3" at 37.13,35.088 h0.8
  text "1" at 49.489,16.728 h0.8
  text "2" at 51.1,16.7 h0.8
  text "REV 1.11" at 3.728,9.345 h1.4 r90
  text "1" at 12.286,2.946 h0.8 r90
  text "9" at 49,2.8 h0.8
  text "10" at 50.647,2.779 h0.8
  text "14" at 10.16,2.54 h0.8 r90
  text "JUC1" at 3.728,2.445 h1.4 r90
PCB Boundary:
  the board outline again, w0.1
  text "PCB boundary coincides with centre-line of tracks" at 4.953,-11.873 h0.75
Gerber ID:
  text ".Layer_Name" at 4.953,-5.873 h0.75
Printout ID:
  text ".Printout_Name" at 4.953,-9.873 h0.75
Dimensions:
  lines w0.1: -1.5,0.5 -1.5,0 -1,0 ; 62,0 62.5,0 62.5,0.5
  lines w0.254: -5.008,1.524 -4.5,0 ; -5.008,37.776 -4.5,39.3 ; -4.754,0 -4.246,0 ; -4.754,39.3 -4.246,39.3 ; -4.5,13.15 -4.5,0 ; -4.5,26.15 -4.5,39.3 ; -3.992,1.524 -4.5,0 ; -3.992,37.776 -4.5,39.3 ; 0,-2.254 0,-1.746 ; 1.524,-2.508 0,-2 ; 1.524,-1.492 0,-2 ; 24.896,-2 0,-2 ; 35.104,-2 60,-2 ; 58.476,-2.508 60,-2 ; 58.476,-1.492 60,-2 ; 60,-2.254 60,-1.746
  text "39.3 (mm)" at -3.586,13.404 h1.52 r90
  text "60 (mm)" at 25.15,-2.914 h1.52
Design Information:
  drawing of 719 lines, arcs and shapes, not listed
  text "JUC1 REV 1.11" at 322.58,252.968 h1.27
  text "DESIGN INFORMATION" at 266.573,252.841 h1.52
  text "BOARD NAME:" at 304.165,252.841 h1.52
  text "BOARD TECHNOLOGY" at 266.573,250.301 h1.52
  text "BOARD SIZE (REFER ALSO PROFILING INFORMATION)" at 314.833,250.301 h1.27
  text "60.0mm" at 317.553,248.027 h1.52
  text "15.748" at 282.372,247.939 h1.52
  text "39.3mm" at 340.553,247.927 h1.52
  text "7.874" at 296.342,247.812 h1.52
  text "5" at 269.399,247.761 h1.52
  text "X" at 333.502,247.253 h1.78
  text "(MIN. TRACK/   PADS  /   CLEARANCE     IN 0.001'')" at 265.049,245.221 h1.27
  text "MINIMUM ANNULAR RING 0.05MM (0.002'') EXTERNAL PER IPC-2221 CLASS 3 LEVEL C AND IS THE" at 266.573,242.681 h1.27
  text "MANUFACTURING REGISTRATION ALLOWANCE" at 266.573,240.395 h1.27
  text "LAND SIZE CALCULATION MINIMUM - NOMINAL HOLE SIZE + 0.508MM (0.020'')" at 266.573,237.601 h1.27
  text "AS INSTRUCTED" at 352.603,233.207 h1.52
  text "X" at 304.216,233.08 h1.52
  text "CIRCUIT TYPE:" at 266.573,233.029 h1.52
  text "SS" at 289.433,233.029 h1.27
  text "DS" at 307.213,233.029 h1.27
  text "X" at 321.818,233.029 h1.52
  text "PTH" at 324.993,233.029 h1.27
  text "ML" at 335.915,233.029 h1.27
  text "No. OFF" at 342.773,233.029 h1.27
  text "FINGER CONNECTOR DIM PER:" at 266.573,229.981 h1.52
  text "AS SHOWN" at 342.773,229.981 h1.27
  text "No. OFF TOTAL" at 283.337,227.187 h1.52
  text "ONE SIDE" at 324.993,227.187 h1.27
  text "BOTH SIDES" at 342.773,226.933 h1.27
  text "VIAS:" at 266.573,224.266 h1.52
  text "NONE" at 278.003,224.266 h1.14
  text "X" at 286.385,224.266 h1.52
  text "FEED THRU'" at 289.433,224.266 h1.14
  text "X" at 304.165,224.266 h1.52
  text "TENTED" at 307.213,224.266 h1.14
  text "BURIED LAYER SEQUENCE" at 324.993,224.266 h1.14
  text "UNIQUE DRILL" at 289.433,221.218 h1.14
  text "2 SIZE" at 307.213,221.218 h1.14
  text "BLIND LAYER SEQUENCE" at 324.993,221.218 h1.14
  text "Layer Stack Manager (Protel)" at 302.006,218.932 h1.27
  text "X" at 339.725,218.932 h1.52
  text "AS SHOWN" at 342.773,218.932 h1.27
  text "LAYER CONSTRUCTION PER:" at 266.573,218.805 h1.52
  text "Protel" at 347.599,216.265 h1.27
  text "(PFW)" at 357.886,216.138 h1.27
  text "ARTWORK:" at 266.573,216.011 h1.52
  text "MANUAL" at 289.433,216.011 h1.27
  text "DIGITISED" at 307.213,216.011 h1.27
  text "X" at 321.945,216.011 h1.52
  text "CAD" at 324.993,216.011 h1.27
  text "TYPE" at 335.915,216.011 h1.27
  text "ARTWORK/PATTERN MASTER LIST" at 266.573,211.312 h1.52
  text "DESCRIPTION" at 267.843,208.899 h1.27
  text "DRAWING No./CAD FILE REF." at 286.512,208.899 h1.27
  text "LAYER NAME" at 327.787,208.899 h1.27
  text "GERBER FILE REF" at 348.539,208.823 h1.27
  text "PCB FILE" at 266.319,206.359 h1.27
  text "JTAG_Interface" at 286.69,206.283 h1.27
  text "PcbDoc" at 317.932,206.283 h1.02
  text "Top Paste Mask" at 326.111,203.819 h1.02
  text "GTP" at 368.732,203.743 h1.27
  text "GERBER FILE" at 266.319,203.692 h1.27
  text "Top Solder Mask" at 326.111,201.33 h1.02
  text "GTS" at 368.732,201.203 h1.27
  text "GERBER FILE" at 266.319,201.152 h1.27
  text "TOP LAYER" at 326.111,198.739 h1.02
  text "GTL" at 368.732,198.663 h1.27
  text "GERBER FILE" at 266.319,198.612 h1.27
  text "BOTTOMLAYER" at 326.111,196.199 h1.02
  text "GBL" at 368.732,196.123 h1.27
  text "GERBER FILE" at 266.319,196.072 h1.27
  text "Bottom Solder Mask" at 326.111,193.71 h1.02
  text "GBS" at 368.732,193.583 h1.27
  text "GERBER FILE" at 266.319,193.532 h1.27
  text "PCB Boundary" at 326.111,191.119 h1.02
  text "GM1" at 368.732,191.043 h1.27
  text "GERBER FILE" at 266.319,190.992 h1.27
  text "APERTURE LIST" at 266.319,188.579 h1.27
  text "APR" at 318.932,188.503 h1.27
  text "DRILL REPORT" at 266.319,186.039 h1.27
  text "DRR" at 318.932,185.963 h1.27
  text "EXCELLON DRILL" at 266.319,183.499 h1.27
  text "TXT" at 318.932,183.423 h1.27
  text "MATERIAL:" at 266.573,150.225 h1.52
  text "GLASS FIBRE EPOXY RESIN NEMA GRADE FR4 (MIL-S-13949H)" at 292.227,149.971 h1.27
  text "X" at 289.56,149.844 h1.52
  text "THICKNESS:" at 274.447,147.05 h1.27
  text "0.8mm" at 292.227,147.05 h1.27
  text "1.2mm" at 309.88,147.05 h1.27
  text "1.6mm" at 327.533,147.05 h1.27
  text "2.4mm" at 345.313,147.05 h1.27
  text "3.2mm" at 363.093,147.05 h1.27
  text "X" at 325.12,146.923 h1.52
  text "TOLERANCE:" at 274.32,144.002 h1.27
  text "IN A/W IPC-D-300G CLASS" at 291.973,144.002 h1.27
  text "3 LEVEL B" at 326.898,144.002 h1.27
  text "OTHER +/-" at 345.313,144.002 h1.27
  text "X" at 289.56,143.875 h1.52
  text "BOW & TWIST:" at 271.907,140.954 h1.27
  text "IN A/W IPC-D-300G CLASS" at 291.973,140.954 h1.27
  text "3 LEVEL B" at 326.898,140.954 h1.27
  text "AS SHOWN" at 345.44,140.827 h1.27
  text "X" at 289.56,140.7 h1.52
  text "COPPER THICKNESS (FINISHED)" at 274.32,137.652 h1.27
  text "OUTER:" at 279.146,135.366 h1.27
  text "18um" at 292.227,135.366 h1.27
  text "35um" at 319.278,135.366 h1.27
  text "70um" at 345.567,135.366 h1.27
  text "X" at 316.535,135.163 h1.52
  text "INNER SIGNAL:" at 270.764,132.318 h1.27
  text "18um" at 292.227,132.318 h1.27
  text "35um" at 319.278,132.318 h1.27
  text "70um" at 345.567,132.318 h1.27
  text "INNER PWR:" at 274.447,129.27 h1.27
  text "18um" at 292.227,129.27 h1.27
  text "35um" at 319.278,129.27 h1.27
  text "70um" at 345.567,129.27 h1.27
  text "STRUCTURE:" at 266.573,126.222 h1.52
  text "REFER" at 292.227,126.222 h1.27
  text "AS PER DRAWING No." at 292.1,123.047 h1.27
  text "AS SHOWN" at 345.44,123.047 h1.27
  text "X" at 342.9,122.92 h1.52
  text "DRILLING:" at 266.573,120.253 h1.52
  text "VIEWED FROM:" at 271.526,117.967 h1.27
  text "COMPONENT SIDE" at 292.227,117.967 h1.14
  text "SOLDER SIDE" at 319.024,117.967 h1.14
  text "X" at 289.56,117.713 h1.52
  text "REFERENCE:" at 273.812,114.919 h1.27
  text "AS SHOWN" at 292.1,114.792 h1.14
  text "PATTERN MASTER LIST" at 319.151,114.792 h1.14
  text "X" at 342.9,114.792 h1.52
  text "NC_DRILL FILES" at 345.44,114.792 h1.14
  text "X" at 289.56,114.665 h1.52
  text "PTH MINIMUM COPPER THICKNESS:" at 279.654,111.871 h1.27
  text "20um" at 319.278,111.871 h1.27
  text "X" at 316.611,111.744 h1.52
  text "OTHER" at 345.44,111.744 h1.27
  text "NPTH:" at 280.162,108.823 h1.27
  text "TENTED" at 292.1,108.696 h1.14
  text "PADS REMOVED" at 319.151,108.696 h1.14
  text "REMOVE PADS" at 345.44,108.696 h1.14
  text "X" at 289.56,108.569 h1.52
  text "2nd DRILL" at 292.1,105.648 h1.14
  text "BOTH" at 319.151,105.648 h1.14
  text "AS SHOWN" at 331.47,105.648 h1.14
  text "NONE" at 345.44,105.648 h1.14
  text "BOARD FINISH:" at 266.573,102.727 h1.52
  text "X" at 289.56,102.6 h1.52
  text "ETCHING" at 292.1,102.6 h1.14
  text "REFER PATTERN MASTER LIST" at 319.151,102.6 h1.14
  text "LEGEND / SCREEN PRINT:" at 286.893,99.679 h1.27
  text "NONE" at 319.151,99.552 h1.14
  text "COMPONENT" at 331.47,99.552 h1.14
  text "SOLDER" at 345.44,99.552 h1.14
  text "X" at 316.611,99.425 h1.52
  text "COLOUR:" at 277.114,96.631 h1.27
  text "WHITE" at 292.1,96.504 h1.14
  text "YELLOW" at 319.151,96.504 h1.14
  text "OTHER" at 345.44,96.504 h1.14
  text "LIQUID PHOTOIMAGEABLE" at 292.1,93.456 h1.14
  text "SCREEN PRINT" at 331.47,93.456 h1.14
  text "MATTE" at 292.1,90.408 h1.14
  text "GLOSS" at 304.8,90.408 h1.14
  text "GREEN" at 319.151,90.408 h1.14
  text "BLUE" at 331.47,90.408 h1.14
  text "G/Y" at 345.44,90.408 h1.14
  text "OTHER" at 356.87,90.408 h1.14
  text "SOLDER MASK COLOUR:" at 266.573,87.487 h1.14
  text "BLACK" at 292.1,87.36 h1.14
  text "GREEN" at 304.8,87.36 h1.14
  text "YELLOW" at 319.151,87.36 h1.14
  text "BLUE" at 331.47,87.36 h1.14
  text "OTHER" at 345.44,87.36 h1.14
  text "X" at 289.433,87.233 h1.52
  text "TRACK FINISH:" at 266.573,84.439 h1.52
  text "X" at 289.56,84.312 h1.52
  text "SELECTIVE SOLDER (HASL)" at 292.1,84.312 h1.14
  text "REFLOW SOLDER" at 331.47,84.312 h1.14
  text "SELECTIVE GOLD" at 292.1,81.264 h1.14
  text "um  (AREA" at 319.151,81.264 h1.14
  text "sq. mm)" at 346.964,81.264 h1.14
  text "REFER PATTERN MASTER LIST" at 292.1,78.216 h1.14
  text "OTHER" at 331.47,78.216 h1.14
  text "EDGE BOARD" at 266.573,75.295 h1.52
  text "1.3um HARD GOLD OVER 5um     NICKEL / TIN-NICKEL" at 292.1,75.168 h1.14
  text "CONTACTS:" at 266.573,73.136 h1.52
  text "HARD FINISH GOLDE PLATE" at 292.1,72.12 h1.14
  text "OTHER" at 331.47,72.12 h1.14
  text "AS SHOWN" at 292.1,69.072 h1.14
  text "REFER" at 331.47,69.072 h1.14
  text "PROFILING:" at 266.573,66.024 h1.52
  text "AS DIMENSIONED, MEASURED AND CUT FROM SPECIFIED DATUM." at 292.1,66.024 h1.14
  text "X" at 289.56,65.897 h1.52
  text "REFER PCB BLANK DWG No." at 292.227,63.103 h1.27
  text "USE PROFILE / ROUTE TAPE SUPPLIED (REFER PATTERN MASTER LIST)" at 292.227,60.055 h1.27
  text "SQUARE CUT" at 292.227,57.007 h1.27
  text "N.C. ROUTE" at 310.007,57.007 h1.27
  text "V. SCORE" at 327.787,57.007 h1.27
  text "BLANK" at 345.567,57.007 h1.27
  text "ACCEPTABILITY:" at 266.573,54.34 h1.52
  text "MATERIALS AND WORKMANSHIP FOR ALL PRINTED WIRING BOARDS TO MEET" at 288.798,54.213 h1.27
  text "OR EXCEED THE REQUIREMENTS OF:" at 288.798,51.419 h1.27
  text "IPC-6011/12 AND IPC-A-600E" at 292.354,48.752 h1.27
  text "1" at 327.914,48.752 h1.27
  text "2" at 336.804,48.752 h1.27
  text "X" at 334.137,48.625 h1.52
  text "X" at 289.687,48.498 h1.52
  text "3" at 345.694,46.593 h1.27
  text "UL CERTIFICATION" at 292.354,45.704 h1.27
  text "AUSTEL" at 327.914,45.704 h1.27
  text "X" at 289.687,45.577 h1.52
  text "ML-P-55110F GRP" at 291.846,42.656 h1.02
  text "A" at 310.134,42.656 h1.27
  text "B" at 319.024,42.656 h1.27
  text "AS2546" at 327.914,42.656 h1.27
  text "OTHER" at 345.694,42.656 h1.27
  text "ADDITIONAL" at 266.573,39.735 h1.52
  text "NONE" at 292.354,39.481 h1.27
  text "SAMPLE PLAN" at 310.134,39.481 h1.27
  text "MIL-P-55110E SERIAL Nos. PER ORDER" at 327.914,39.481 h1.27
  text "REQUIREMENTS:" at 266.573,37.322 h1.52
  text "NONE" at 292.354,36.433 h1.27
  text "ML-P-55110F GRP" at 309.626,36.433 h1.02
  text "A" at 327.914,36.433 h1.27
  text "B" at 336.804,36.433 h1.27
  text "IPC CLASS:" at 342.773,36.433 h1.27
  text "1" at 358.267,36.433 h1.27
  text "2" at 364.617,36.433 h1.27
  text "3" at 370.967,36.433 h1.27
  text "QUALITY RELEASE REPORT" at 310.134,33.385 h1.27
  text "OTHER" at 350.647,33.385 h1.27
  text "PER ORDER" at 359.156,33.258 h1.27
  text "X" at 347.98,33.131 h1.52
  text "NONE" at 310.134,30.337 h1.27
  text "REQUIRED" at 327.914,30.337 h1.27
  text "PER ORDER" at 350.774,30.337 h1.27
  text "ELECTRICAL TEST:" at 266.573,30.21 h1.52
  text "X" at 325.247,30.21 h1.52
  text "NONE" at 310.134,27.289 h1.27
  text "1 SIDE" at 327.787,27.289 h1.14
  text "2 SIDES" at 338.963,27.289 h1.14
  text "MIN. PITCH" at 350.647,27.289 h1.27
  text "0.65mm" at 364.236,27.289 h1.27
  text "SURFACE MOUNT:" at 266.573,27.162 h1.52
  text "X" at 325.298,27.086 h1.52
  text "NONE" at 310.134,24.241 h1.27
  text "FOIL" at 327.914,24.241 h1.27
  text "LEGEND" at 339.344,24.241 h1.27
  text "REFER" at 350.647,24.241 h1.27
  text "MANUFACTURER'S ID/LOGO:" at 266.573,24.114 h1.52
  text "ISO9001/AS3901" at 313.944,21.193 h1.27
  text "NONE" at 350.647,21.193 h1.27
  text "MANUFACTURER'S ACCREDITATION:" at 266.573,21.066 h1.52
  text "X" at 311.277,21.066 h1.52
  text "PER ORDER" at 310.134,18.145 h1.27
  text "REFER" at 327.914,18.145 h1.27
  text "PACKAGING AND HANDLING:" at 266.573,18.018 h1.52
  text "X" at 307.467,17.891 h1.52
Sheet:
  drawing of 1882 lines, arcs and shapes, not listed
  text "1" at 8.67,258.318 h1.78
  text "2" at 57.709,258.318 h1.78
  text "3" at 106.968,258.318 h1.78
  text "4" at 156.261,258.318 h1.78
  text "5" at 205.537,258.318 h1.78
  text "6" at 254.559,258.318 h1.78
  text "7" at 304.089,258.318 h1.78
  text "8" at 353.111,258.318 h1.78
  text "A" at -13.462,224.333 h1.78
  text "A" at 375.158,224.333 h1.78
  text "B" at -13.462,153.721 h1.78
  text "B" at 375.158,153.721 h1.78
  text "C" at -13.462,83.109 h1.78
  text "C" at 375.158,83.109 h1.78
  text "D" at -13.462,13.005 h1.78
  text "D" at 375.158,13.005 h1.78
  text "ENGINEER:" at 260.223,12.827 h1.14
  text "TITLE:" at 298.323,12.827 h1.14
  text "PCB DESIGNER:" at 260.223,5.334 h1.14
  text "DATE:" at 260.223,-2.413 h1.14
  text "PART NO.:" at 298.323,-2.413 h1.14
  text "REV:" at 351.663,-2.413 h1.14
  text "Altium Limited" at 227.203,-4.953 h1.78
  text ".PRINT_DATE" at 261.493,-5.461 h1.78
  text "12a Rodborough Rd" at 227.203,-7.493 h1.78
  text "Frenchs Forest" at 227.203,-10.033 h1.78
  text "FILE NAME:" at 260.223,-10.033 h1.14
  text "DWG NO:" at 298.323,-10.033 h1.14
  text "SCALE:" at 351.663,-10.033 h1.14
  text "NSW 2086" at 227.203,-12.573 h1.78
  text ".PCB_FILE_NAME_NO_PATH" at 261.493,-13.081 h1.78
  text "1" at 8.67,-18.542 h1.78
  text "2" at 57.709,-18.542 h1.78
  text "3" at 106.968,-18.542 h1.78
  text "4" at 156.261,-18.542 h1.78
  text "5" at 205.537,-18.542 h1.78
  text "6" at 254.559,-18.542 h1.78
  text "7" at 304.089,-18.542 h1.78
  text "8" at 353.111,-18.542 h1.78
Drill Drawing:
  text ".Legend" at 4.953,-7.873 h0.75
